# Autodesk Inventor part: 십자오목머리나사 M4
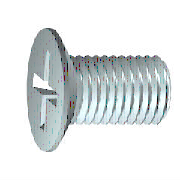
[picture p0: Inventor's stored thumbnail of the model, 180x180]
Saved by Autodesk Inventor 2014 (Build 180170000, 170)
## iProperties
IsCustomPart: 0
Created: 2012-02
Part Number: 십자오목머리나사 M4
Material: 강철, 연강
Description: 십자 오목 머리 나사
Document SubType Name: Modeling
Standard: KS B 1023
Designer: mduedu
Standards Organization: KS
Language: ko-KR
Size Designation: A  M 4 x 12 - H
Categories: <MemberInstance><Categories><Category DisplayName="조임쇠" InternalName="e4da775c-781d-43d5-af7c-5136215cf5a6" Mnemonic="FSTN"><Category DisplayName="볼트" InternalN
Density: 7.86 g/cm^3
Mass: 1.50482 g
Surface Area: 2.78557 cm^2
Volume: 0.191453 cm^3
Appearance: 보라색
Author: mduedu
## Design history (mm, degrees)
body "Solid1"
sketch "스케치1"
  geometry: L1 (2.6, 0)-(12, 0); L2 (12, 0)-(12, 2); L3 (12, 2)-(4.1, 2); L4 (4.1, 2)-(3.671, 1.785); L5 (3.671, 1.785)-(2.7, 1.785); L6 (0, 4.2)-(0, 2.4); L7 (0, 2.4)-(1.801, 1.502); L8 (1.801, 1.502)-(2.6, 0); L9 (-2.4, 0)-(14.4, 0) reference; L10 (0, -0.84)-(0, 5.04) reference; L11 (0, 4.2)-(0.285, 4.2); L12 (0.285, 4.2)-(2.7, 1.785); L13 (4.1, 2)-(2.485, 2)
  constraints: 22 end point, 3 parallel, 3 perpendicular, 2 collinear, 1 horizontal, 1 point on line
  dimensions: "d1" = 7.9 distance of L2.end L3.end (= GEL); "d2" = 4 diameter of L3 L1 (= GD); "d3" = 3.57058 diameter of L5 L1 (= BDM); "d4" = 4.8 diameter of L6.end L1 (= SDM); "d5" = 26.5 deg angle of L7 L1; "d6" = 62 deg angle of L8 L1; "d7" = 2.6 distance from line of L1.start L6 (= INTI); "d8" = 0.42941 horizontal distance of L4.end L3.end (= GAL); "d12" = 8.4 diameter of L11 L1 (= KOD); "d13" = 45 deg angle of L12 L1 (= 0.5 x SEWI); "d15" = 12 distance between parallel lines of L2 L6 (= NLG); "d24" = 2.7 distance from line of L5.end L6 (= KOH)
revolve "본체" stored, may be unused: angle "d16" = 90 deg
sketch "스케치2"
  geometry: L1 (0, 2.4)-(0, 0); L2 (0, 0)-(2.4, 0); L3 (0, 0)-(1.697, 1.697); L4 (0.312, 2.38)-(0.408, 0.734); L5 (2.38, 0.312)-(0.734, 0.408); L6 (0, -5.88)-(0, 5.88) reference; L7 (-5.88, 0)-(5.88, 0) reference; L8 (2.38, -0.312)-(0.734, -0.408); L9 (0.312, -2.38)-(0.408, -0.734); L10 (-0.312, -2.38)-(-0.408, -0.734); L11 (-2.38, -0.312)-(-0.734, -0.408); L12 (-2.38, 0.312)-(-0.734, 0.408); L13 (-0.312, 2.38)-(-0.408, 0.734); A1 r 0.72 centre (0, 0) between (0.72, 0) and (0, 0.72); A2 r 0.84 centre (0, 0) between (0.84, 0) and (0, 0.84); A3 r 2.4 centre (0, 0) between (2.38, 0.312) and (0.312, 2.38); A4 r 2.4 centre (0, 0) between (0.312, 2.38) and (0, 2.4); A5 r 2.4 centre (0, 0) between (2.4, 0) and (2.38, 0.312); A6 r 2.4 centre (0, 0) between (0, -2.4) and (0.312, -2.38); A7 r 2.4 centre (0, 0) between (0.312, -2.38) and (2.38, -0.312); A8 r 2.4 centre (0, 0) between (2.38, -0.312) and (2.4, 0); A9 r 2.4 centre (0, 0) between (0, 2.4) and (-0.312, 2.38); A10 r 2.4 centre (0, 0) between (-0.312, 2.38) and (-2.38, 0.312); A11 r 2.4 centre (0, 0) between (-2.38, 0.312) and (-2.4, 0); A12 r 2.4 centre (0, 0) between (-2.4, 0) and (-2.38, -0.312); A13 r 2.4 centre (0, 0) between (-2.38, -0.312) and (-0.312, -2.38); A14 r 2.4 centre (0, 0) between (-0.312, -2.38) and (0, -2.4); A15 r 0.347 centre (0.755, 0.755) between (0.408, 0.734) and (0.734, 0.408); A16 r 0.347 centre (0.755, -0.755) between (0.734, -0.408) and (0.408, -0.734); A17 r 0.347 centre (-0.755, -0.755) between (-0.408, -0.734) and (-0.734, -0.408); A18 r 0.347 centre (-0.755, 0.755) between (-0.734, 0.408) and (-0.408, 0.734); 3 further points
  constraints: 41 point on circle, 22 end point, 22 symmetric about line, 18 centre point, 11 coincident, 4 point on line, 3 tangent, 2 collinear, 1 perpendicular, 1 vertical, 19 other
  dimensions: "d17" = 1.44 diameter of A1 (= 0.3 x SDM); "d18" = 1.68 diameter of A2 (= 0.35 x SDM); "d19" = 4.8 diameter of A3 (= SDM); "d20" = 45 deg angle of L3 L2; "d21" = 0.3115 distance from line of L4.start L1 (= 0.5 x SBR)
extrude "슬롯" join sketch "스케치2" taper "d22" = 5 deg; stored distance "d79" = 25.4
fillet "모깎기1" dims "d23" = 0.1246 (= 0.2 x SBR)
feature "스레드" dims "d10" = 7.9 (= GEL), "d11" = 0
chamfer "모따기1" distance "d25" = 0.42941 (= -0.5 x SPD + 0.5 x GD); stored, may be unused: second distance "d26" = 0.21471 (= 0.5 x GAL), angle "d88" = 45 deg
workplane "Work Plane2"
other parameters: "NLG" = 12 [user parameter; used in 1 equation term], "GEL" = 7.9 [user parameter; used in 2 equation terms], "GAL" = 0.42941 (= 0.61345 x PTC) [user parameter; used in 3 equation terms], "SPD" = 3.14117 (= NND - 1.2269 x PTC) [user parameter; used in 1 equation term], "KOD" = 8.4 [user parameter; used in 1 equation term], "KOH" = 2.7 [user parameter; used in 1 equation term], "SBR" = 0.623 [user parameter; used in 2 equation terms], "INTI" = 2.6 [user parameter; used in 1 equation term], "SDM" = 4.8 [user parameter; used in 5 equation terms], "GD" = 4 (= NND) [user parameter; used in 2 equation terms], "BDM" = 3.57058 (= NND - GAL) [user parameter; used in 1 equation term], "SEWI" = 90 deg [user parameter; used in 1 equation term], "d9" = 4.8 (= SDM), "d27" = 0, "d91" = 0, "d92" = 0, "GUL" = 0.42941 (= 0.61345 x PTC) [user parameter], "TOA" = 30 deg [user parameter], "EPV" = 4.7 [user parameter], "THREADDIA" = 4 [user parameter; used in 1 equation term], "TPU" = 14.28571 (computed from PTC) [user parameter], "PTC" = 0.7 [user parameter; used in 5 equation terms], "NND" = 4 [user parameter; used in 3 equation terms], "GD1" = 3.14117 (= THREADDIA - 1.2269 x PTC) [user parameter]
